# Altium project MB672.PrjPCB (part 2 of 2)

## Sheet MCU.SchDoc: STM3210E-EVAL MCU
size A3; Date: Not used; ApprovedBy: Not used; CheckedBy: Not used; Author: Not used; CompanyName: STMicroelectronics; DrawnBy: Not used; Engineer: Not used; Organization: Not used; Address1: Not used; Address2: Not used; Address3: Not used; Address4: Not used; DocumentNumber: Not used; Revision: Not used; SheetNumber: 3; SheetTotal: 12
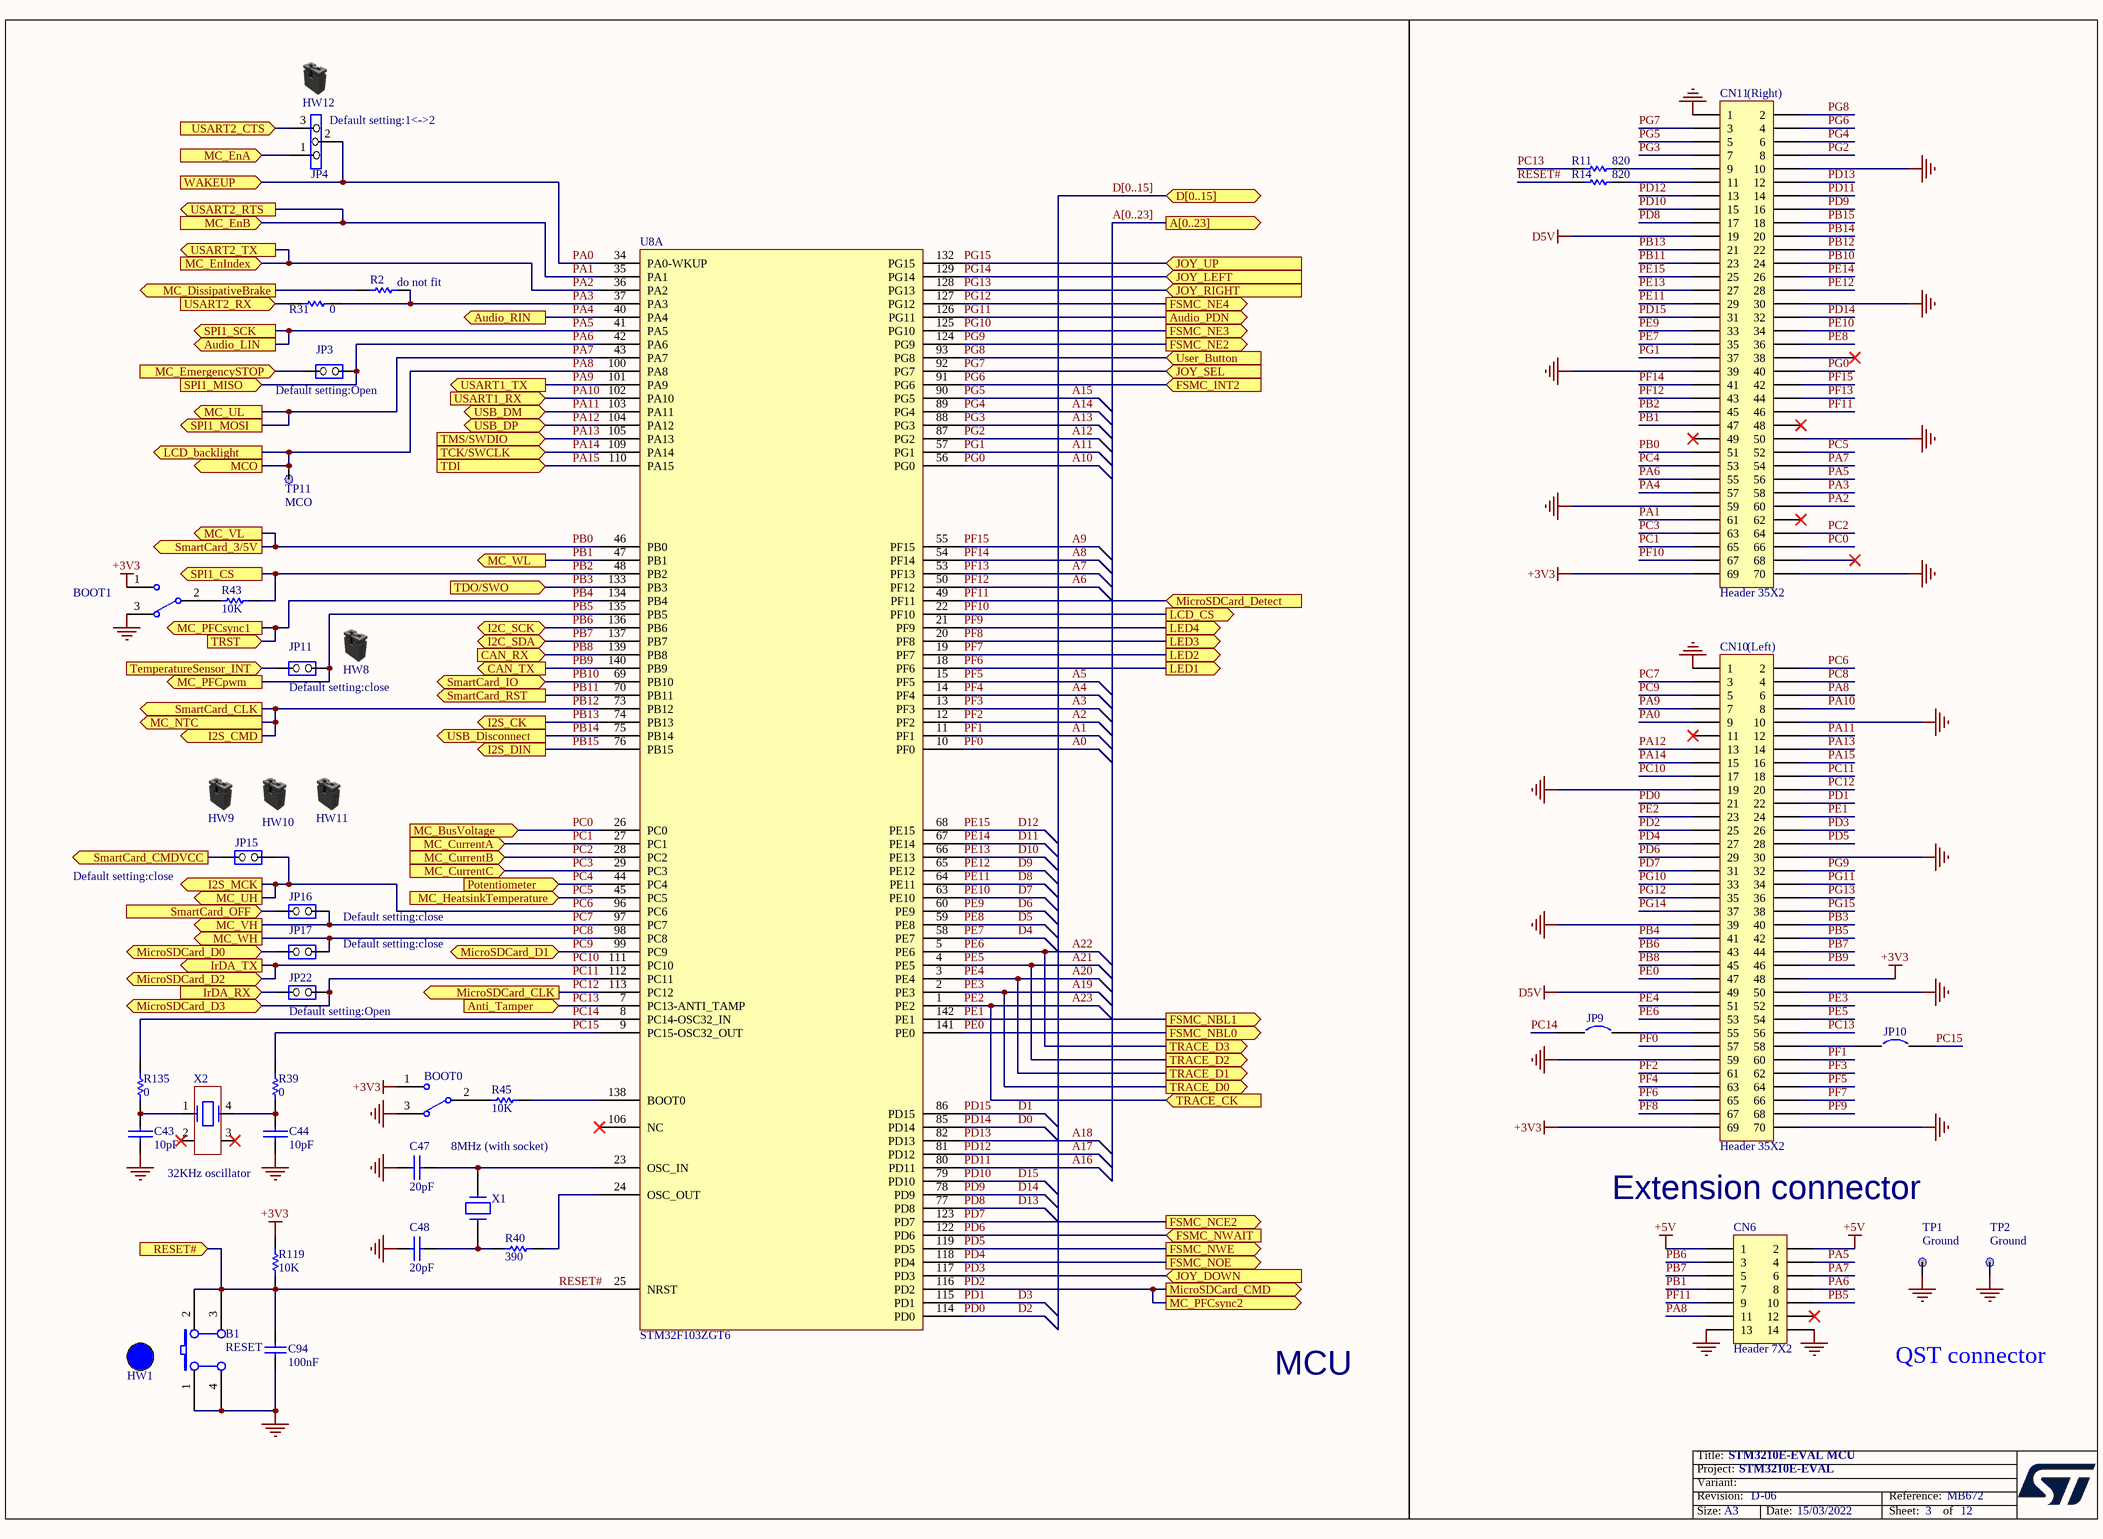
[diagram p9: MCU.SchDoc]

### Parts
B1  RESET  [PB10]
BOOT0  (no value)  [SIP3]
BOOT1  (no value)  [SIP3]
C43  10pF  [0603]
C44  10pF  [0603]
C47  20pF  [0603]
C48  20pF  [0603]
C94  100nF  [0603P]
CN6  Header 7X2  [HDR2X7]
CN10  Header 35X2
CN11  Header 35X2
HW1  BUTTON_HAT_BLUE  (value not drawn)  (mechanical)
HW8  Shunt Black 2.54mm  (value not drawn)  (mechanical)
HW9  Shunt Black 2.54mm  (value not drawn)  (mechanical)
HW10  Shunt Black 2.54mm  (value not drawn)  (mechanical)
HW11  Shunt Black 2.54mm  (value not drawn)  (mechanical)
HW12  Shunt Black 2.54mm  (value not drawn)  (mechanical)
JP3  (no value)  [SIP2]
JP4  (no value)  [SIP3]
JP9  (no value)  [SPST-2]
JP10  (no value)  [SPST-2]
JP11  (no value)  [SIP2]
JP15  (no value)  [SIP2]
JP16  (no value)  [SIP2]
JP17  (no value)  [SIP2]
JP22  (no value)  [SIP2]
R2  do not fit  [0603]
R11  820  [0603]
R14  820  [0603]
R31  0  [0603]
R39  0  [0805]
R40  390  [0603]
R43  10K  [0603]
R45  10K  [0603]
R119  10K  [0603]
R135  0  [0805]
TP1  Ground  [TP]
TP2  Ground  [TP]
TP11  MCO  [TP]
U8  STM32F103ZGT6  (part A of 2)
X1  8MHz (with socket)  [XTAL1]
X2  32KHz oscillator  [SM8]

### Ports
A[0..23] (out), Anti_Tamper (in), Audio_LIN (out), Audio_PDN (out), Audio_RIN (out), CAN_RX (in), CAN_TX (out), D[0..15] (bidir), FSMC_INT2 (in), FSMC_NBL0 (out), FSMC_NBL1 (out), FSMC_NCE2 (out), FSMC_NE2 (out), FSMC_NE3 (out), FSMC_NE4 (out), FSMC_NOE (out), FSMC_NWAIT (in), FSMC_NWE (out), I2C_SCK (bidir), I2C_SDA (bidir), I2S_CK (out), I2S_CMD (out), I2S_DIN (out), I2S_MCK (out), IrDA_RX (in), IrDA_TX (out), JOY_DOWN (in), JOY_LEFT (in), JOY_RIGHT (in), JOY_SEL (in), JOY_UP (in), LCD_backlight (out), LCD_CS (out), LED1 (out), LED2 (out), LED3 (out), LED4 (out), MC_BusVoltage (in), MC_CurrentA (in), MC_CurrentB (in), MC_CurrentC (in), MC_DissipativeBrake (out), MC_EmergencySTOP (in), MC_EnA (in), MC_EnB (in), MC_EnIndex (in), MC_HeatsinkTemperature (in), MC_NTC (out), MC_PFCpwm (out), MC_PFCsync1 (out), MC_PFCsync2 (out), MC_UH (out), MC_UL (out), MC_VH (out), MC_VL (out), MC_WH (out), MC_WL (out), MCO (out), MicroSDCard_CLK (out), MicroSDCard_CMD (out), MicroSDCard_D0 (bidir), MicroSDCard_D1 (bidir), MicroSDCard_D2 (bidir), MicroSDCard_D3 (bidir), MicroSDCard_Detect (in), Potentiometer (in), RESET# (in), SmartCard_3/5V (out), SmartCard_CLK (out), SmartCard_CMDVCC (out), SmartCard_IO (bidir), SmartCard_OFF (in), SmartCard_RST (out), SPI1_CS (out), SPI1_MISO (in), SPI1_MOSI (out), SPI1_SCK (out), TCK/SWCLK (in), TDI (in), TDO/SWO (in), TemperatureSensor_INT (in), TMS/SWDIO (in), TRACE_CK (in), TRACE_D0 (out), TRACE_D1 (out), TRACE_D2 (out), TRACE_D3 (out), TRST (in), USART1_RX (in), USART1_TX (out), USART2_CTS (in), USART2_RTS (out), USART2_RX (in), USART2_TX (out), USB_Disconnect (out), USB_DM (bidir), USB_DP (bidir), User_Button (in), WAKEUP (in)

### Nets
+3V3: BOOT0.1 BOOT1.1 CN10.48 CN10.69 CN11.69 R119.2
+5V: CN6.1 CN6.2
D5V: CN10.49 CN11.19
GND: B1.1(A0) B1.4(A1) BOOT0.3 BOOT1.3 C43.2 C44.2 C47.2 C48.2 C94.1 CN6.13 CN6.14 CN10.1 CN10.10 CN10.19 CN10.30 CN10.39 CN10.50 CN10.59 CN10.70 CN11.1 CN11.10 CN11.30 CN11.39 CN11.50 CN11.59 CN11.70 TP1.1 TP2.1
A0: CN10.57 U8.10(PF0)  [also labelled PF0]
A1: CN10.60 U8.11(PF1)  [also labelled PF1]
A2: CN10.61 U8.12(PF2)  [also labelled PF2]
A3: CN10.62 U8.13(PF3)  [also labelled PF3]
A4: CN10.63 U8.14(PF4)  [also labelled PF4]
A5: CN10.64 U8.15(PF5)  [also labelled PF5]
A6: CN11.43 U8.50(PF12)  [also labelled PF12]
A7: CN11.44 U8.53(PF13)  [also labelled PF13]
A8: CN11.41 U8.54(PF14)  [also labelled PF14]
A9: CN11.42 U8.55(PF15)  [also labelled PF15]
A10: CN11.40 U8.56(PG0)  [also labelled PG0]
A11: CN11.37 U8.57(PG1)  [also labelled PG1]
A12: CN11.8 U8.87(PG2)  [also labelled PG2]
A13: CN11.7 U8.88(PG3)  [also labelled PG3]
A14: CN11.6 U8.89(PG4)  [also labelled PG4]
A15: CN11.5 U8.90(PG5)  [also labelled PG5]
A16: CN11.14 U8.80(PD11)  [also labelled PD11]
A17: CN11.13 U8.81(PD12)  [also labelled PD12]
A18: CN11.12 U8.82(PD13)  [also labelled PD13]
A19: CN10.52 U8.2(PE3) ; port TRACE_D0  [also labelled PE3]
A20: CN10.51 U8.3(PE4) ; port TRACE_D1  [also labelled PE4]
A21: CN10.54 U8.4(PE5) ; port TRACE_D2  [also labelled PE5]
A22: CN10.53 U8.5(PE6) ; port TRACE_D3  [also labelled PE6]
A23: CN10.23 U8.1(PE2) ; port TRACE_CK  [also labelled PE2]
D0: CN11.32 U8.85(PD14)  [also labelled PD14]
D1: CN11.31 U8.86(PD15)  [also labelled PD15]
D2: CN10.21 U8.114(PD0)  [also labelled PD0]
D3: CN10.22 U8.115(PD1)  [also labelled PD1]
D4: CN11.35 U8.58(PE7)  [also labelled PE7]
D5: CN11.36 U8.59(PE8)  [also labelled PE8]
D6: CN11.33 U8.60(PE9)  [also labelled PE9]
D7: CN11.34 U8.63(PE10)  [also labelled PE10]
D8: CN11.29 U8.64(PE11)  [also labelled PE11]
D9: CN11.28 U8.65(PE12)  [also labelled PE12]
D10: CN11.27 U8.66(PE13)  [also labelled PE13]
D11: CN11.26 U8.67(PE14)  [also labelled PE14]
D12: CN11.25 U8.68(PE15)  [also labelled PE15]
D13: CN11.17 U8.77(PD8)  [also labelled PD8]
D14: CN11.16 U8.78(PD9)  [also labelled PD9]
D15: CN11.15 U8.79(PD10)  [also labelled PD10]
PA0: CN10.9 JP4.2 U8.34(PA0-WKUP) ; port WAKEUP
PA1: CN11.61 U8.35(PA1) ; port USART2_RTS, port MC_EnB
PA2: CN11.60 U8.36(PA2) ; port USART2_TX, port MC_EnIndex
PA3: CN11.58 R2.1 R31.1 U8.37(PA3)
PA4: CN11.57 U8.40(PA4) ; port Audio_RIN
PA5: CN6.4 CN11.56 U8.41(PA5) ; port SPI1_SCK, port Audio_LIN
PA6: CN6.8 CN11.55 JP3.1(COMMON) U8.42(PA6) ; port SPI1_MISO
PA7: CN6.6 CN11.54 U8.43(PA7) ; port MC_UL, port SPI1_MOSI
PA8: CN6.11 CN10.6 TP11.1 U8.100(PA8) ; port LCD_backlight, port MCO
PA9: CN10.7 U8.101(PA9) ; port USART1_TX
PA10: CN10.8 U8.102(PA10) ; port USART1_RX
PA11: CN10.12 U8.103(PA11) ; port USB_DM
PA12: CN10.13 U8.104(PA12) ; port USB_DP
PA13: CN10.14 U8.105(PA13) ; port TMS/SWDIO
PA14: CN10.15 U8.109(PA14) ; port TCK/SWCLK
PA15: CN10.16 U8.110(PA15) ; port TDI
PB0: CN11.51 U8.46(PB0) ; port MC_VL, port SmartCard_3/5V
PB1: CN6.7 CN11.47 U8.47(PB1) ; port MC_WL
PB2: CN11.45 R43.1 U8.48(PB2) ; port SPI1_CS
PB3: CN10.40 U8.133(PB3) ; port TDO/SWO
PB4: CN10.41 U8.134(PB4) ; port TRST, port MC_PFCsync1
PB5: CN6.10 CN10.42 JP11.1(COMMON) U8.135(PB5) ; port MC_PFCpwm
PB6: CN6.3 CN10.43 U8.136(PB6) ; port I2C_SCK
PB7: CN6.5 CN10.44 U8.137(PB7) ; port I2C_SDA
PB8: CN10.45 U8.139(PB8) ; port CAN_RX
PB9: CN10.46 U8.140(PB9) ; port CAN_TX
PB10: CN11.24 U8.69(PB10) ; port SmartCard_IO
PB11: CN11.23 U8.70(PB11) ; port SmartCard_RST
PB12: CN11.22 U8.73(PB12) ; port I2S_CMD, port MC_NTC, port SmartCard_CLK
PB13: CN11.21 U8.74(PB13) ; port I2S_CK
PB14: CN11.20 U8.75(PB14) ; port USB_Disconnect
PB15: CN11.18 U8.76(PB15) ; port I2S_DIN
PC0: CN11.66 U8.26(PC0) ; port MC_BusVoltage
PC1: CN11.65 U8.27(PC1) ; port MC_CurrentA
PC2: CN11.64 U8.28(PC2) ; port MC_CurrentB
PC3: CN11.63 U8.29(PC3) ; port MC_CurrentC
PC4: CN11.53 U8.44(PC4) ; port Potentiometer
PC5: CN11.52 U8.45(PC5) ; port MC_HeatsinkTemperature
PC6: CN10.2 JP15.1(COMMON) U8.96(PC6) ; port MC_UH, port I2S_MCK
PC7: CN10.3 JP16.1(COMMON) U8.97(PC7) ; port MC_VH
PC8: CN10.4 JP17.1(COMMON) U8.98(PC8) ; port MC_WH
PC9: CN10.5 U8.99(PC9) ; port MicroSDCard_D1
PC10: CN10.17 U8.111(PC10) ; port IrDA_TX, port MicroSDCard_D2
PC11: CN10.18 JP22.1(COMMON) U8.112(PC11) ; port MicroSDCard_D3
PC12: CN10.20 U8.113(PC12) ; port MicroSDCard_CLK
PC13: CN10.56 R11.1 U8.7(PC13-ANTI_TAMP) ; port Anti_Tamper
PC14: JP9.1 R135.2 U8.8(PC14-OSC32_IN)
PC15: JP10.2 R39.2 U8.9(PC15-OSC32_OUT)
PD2: CN10.25 U8.116(PD2) ; port MC_PFCsync2, port MicroSDCard_CMD
PD3: CN10.26 U8.117(PD3) ; port JOY_DOWN
PD4: CN10.27 U8.118(PD4) ; port FSMC_NOE
PD5: CN10.28 U8.119(PD5) ; port FSMC_NWE
PD6: CN10.29 U8.122(PD6) ; port FSMC_NWAIT
PD7: CN10.31 U8.123(PD7) ; port FSMC_NCE2
PE0: CN10.47 U8.141(PE0) ; port FSMC_NBL0
PE1: CN10.24 U8.142(PE1) ; port FSMC_NBL1
PF6: CN10.65 U8.18(PF6) ; port LED1
PF7: CN10.66 U8.19(PF7) ; port LED2
PF8: CN10.67 U8.20(PF8) ; port LED3
PF9: CN10.68 U8.21(PF9) ; port LED4
PF10: CN11.67 U8.22(PF10) ; port LCD_CS
PF11: CN6.9 CN11.46 U8.49(PF11) ; port MicroSDCard_Detect
PG6: CN11.4 U8.91(PG6) ; port FSMC_INT2
PG7: CN11.3 U8.92(PG7) ; port JOY_SEL
PG8: CN11.2 U8.93(PG8) ; port User_Button
PG9: CN10.32 U8.124(PG9) ; port FSMC_NE2
PG10: CN10.33 U8.125(PG10) ; port FSMC_NE3
PG11: CN10.34 U8.126(PG11) ; port Audio_PDN
PG12: CN10.35 U8.127(PG12) ; port FSMC_NE4
PG13: CN10.36 U8.128(PG13) ; port JOY_RIGHT
PG14: CN10.37 U8.129(PG14) ; port JOY_LEFT
PG15: CN10.38 U8.132(PG15) ; port JOY_UP
RESET#: B1.2(B0) B1.3(B1) C94.2 R14.2 R119.1 U8.25(NRST) ; port RESET#
NetBOOT0_2: BOOT0.2 R45.2
NetBOOT1_2: BOOT1.2 R43.2
NetC1_2: JP4.1 ; port MC_EnA
NetC43_1: C43.1 R135.1 X2.1
NetC44_1: C44.1 R39.1 X2.4
NetC47_1: C47.1 U8.23(OSC_IN) X1.2
NetC48_1: C48.1 R40.2 X1.1
NetCN1_23: R2.2 ; port MC_DissipativeBrake
NetCN10_55: CN10.55 JP9.2
NetCN10_58: CN10.58 JP10.1
NetCN11_9: CN11.9 R11.2
NetCN11_11: CN11.11 R14.1
NetCN13_7: JP17.2(NO) ; port MicroSDCard_D0
NetJP3_2: JP3.2(NO) ; port MC_EmergencySTOP
NetJP4_3: JP4.3 ; port USART2_CTS
NetJP11_2: JP11.2(NO) ; port TemperatureSensor_INT
NetJP15_2: JP15.2(NO) ; port SmartCard_CMDVCC
NetJP16_2: JP16.2(NO) ; port SmartCard_OFF
NetJP22_2: JP22.2(NO) ; port IrDA_RX
NetR29_2: R31.2 ; port USART2_RX
NetR40_1: R40.1 U8.24(OSC_OUT)
NetR45_1: R45.1 U8.138(BOOT0)

Not connected (* = marked no-connect by the designer): CN6 12*; CN10 11*; CN11 38* 48* 49* 62* 68*; U8 106(NC)*; X2 2* 3*

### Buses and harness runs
bus A[0..23] = port A[0..23]
bus D[0..15] = port D[0..15]

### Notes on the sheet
- (near JP4) Default setting:1<->2
- (near CN11) (Right)
- (near JP3) Default setting:Open
- (near CN10) (Left)
- (near JP11) Default setting:close
- (near JP15) Default setting:close
- Default setting:close
- (near JP22) Default setting:Open
- Extension connector
- MCU
- QST connector

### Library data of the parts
B1 = SW PUSHBUTTON: SE PUSHBUTTON
BOOT0 BOOT1 = SW-SPDT: SPDT Subminiature Toggle Switch, Right Angle Mounting, Vertical Actuation; Revision 1: Jul-2002: Re-released for DXP Platform.; Revision 2: 17-Dec-2003: Schematic revised, PCB Footprint replaced.
C43 C44 C47 C48 = CAP: Capacitor
C94 = CAP: Capacitor; Value: 100pF
CN6 = Header 7X2: Header, 7-Pin, Dual row
CN10 CN11 = Header35X2
JP3 JP11 JP15-JP17 JP22 = JP2
JP4 = Jumper3
JP9 JP10 = Circuit Breaker
R2 R31 R43 R45 R119 = res1: Resistor; Value: 1K
R11 R14 R39 R40 R135 = Res1: Resistor; Value: 1K
TP1 TP2 TP11 = TP
U8 = BigPiranha_new
X1 = CRYSTAL
X2 = MC306

## Sheet SD&Smart_Card.SchDoc: STM3210E-EVAL SD&Smart Card
size A4; Date: Not used; ApprovedBy: Not used; CheckedBy: Not used; Author: Not used; CompanyName: STMicroelectronics; DrawnBy: Not used; Engineer: Not used; Organization: Not used; Address1: Not used; Address2: Not used; Address3: Not used; Address4: Not used; DocumentNumber: Not used; Revision: Not used; SheetNumber: 5; SheetTotal: 12
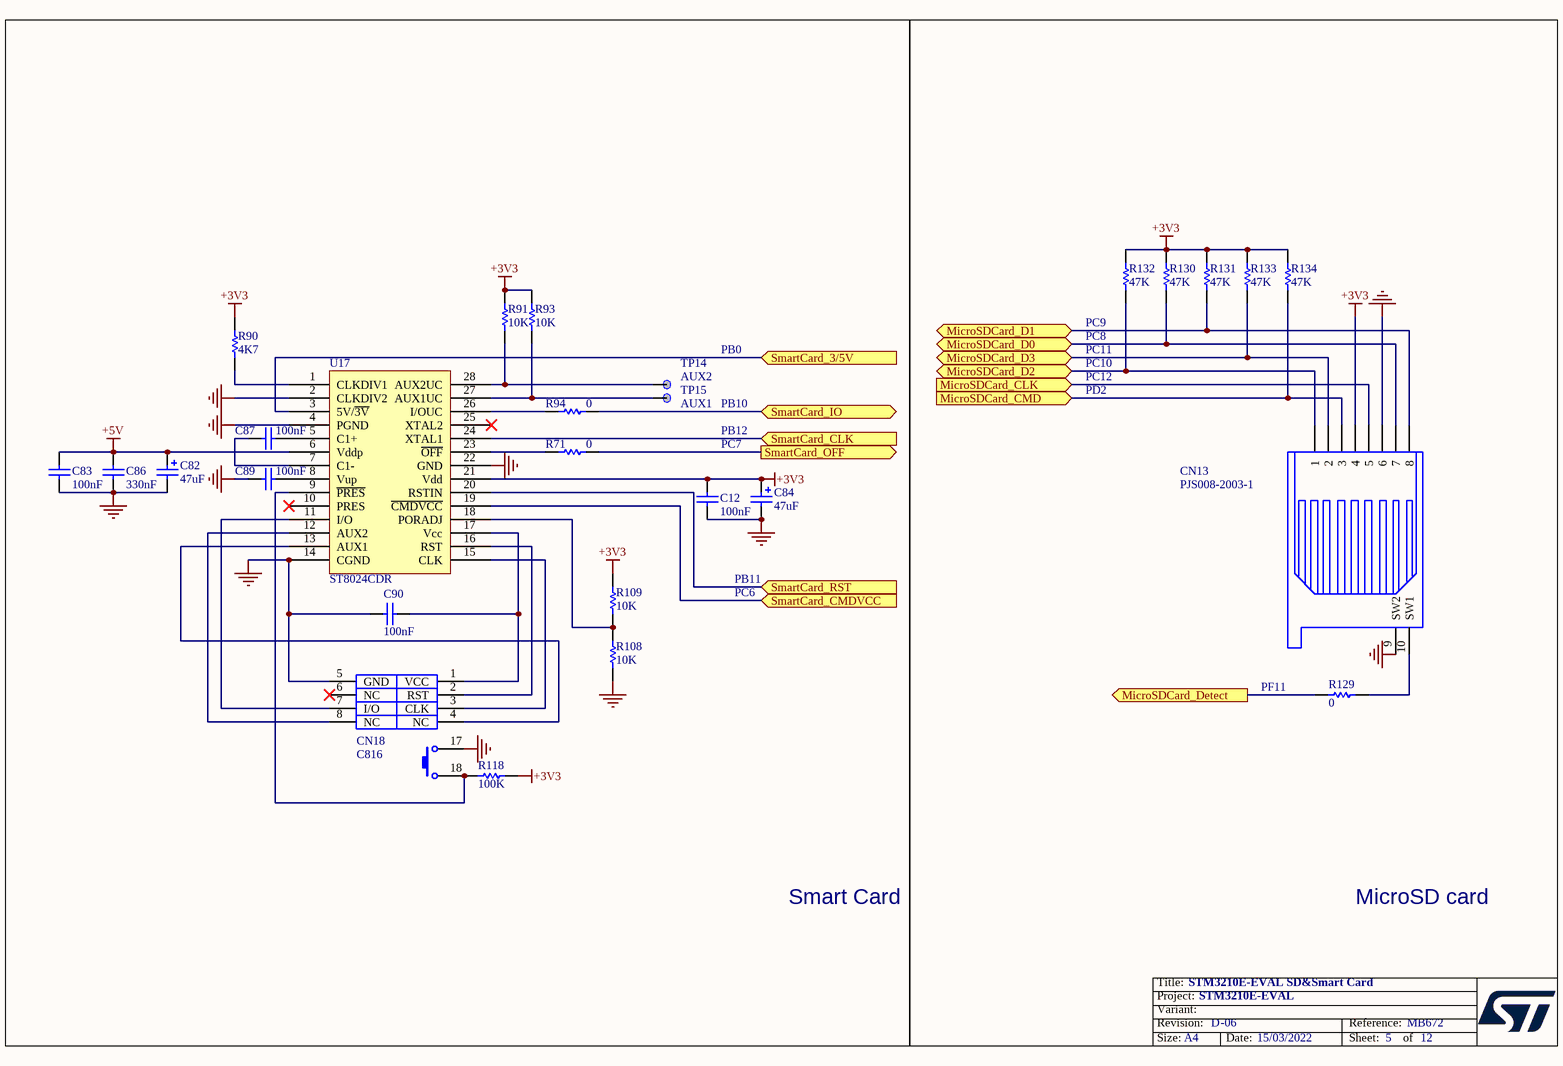
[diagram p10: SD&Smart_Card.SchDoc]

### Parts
C12  100nF  [0603P]
C82  47uF  [TAN-B]
C83  100nF  [0603P]
C84  47uF  [TAN-B]
C86  330nF  [0603]
C87  100nF  [0603P]
C89  100nF  [0603P]
C90  100nF  [0603P]
CN13  PJS008-2003-1  [MSD(PJS008)]
CN18  C816  [SAM(C816)]
R71  0  [0805]
R90  4K7  [0603]
R91  10K  [0603]
R93  10K  [0603]
R94  0  [0805]
R108  10K  [0603]
R109  10K  [0603]
R118  100K  [0603]
R129  0  [0603]
R130  47K  [0805]
R131  47K  [0805]
R132  47K  [0805]
R133  47K  [0805]
R134  47K  [0805]
TP14  AUX2  [TP]
TP15  AUX1  [TP]
U17  ST8024CDR  [SO28]

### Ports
MicroSDCard_CLK (in), MicroSDCard_CMD (in), MicroSDCard_D0 (bidir), MicroSDCard_D1 (bidir), MicroSDCard_D2 (bidir), MicroSDCard_D3 (bidir), MicroSDCard_Detect (out), SmartCard_3/5V (in), SmartCard_CLK (in), SmartCard_CMDVCC (in), SmartCard_IO (bidir), SmartCard_OFF (out), SmartCard_RST (in)

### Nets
+3V3: C12.1 C84.1 CN13.4 R90.1 R91.1 R93.1 R109.1 R118.1 R130.1 R131.1 R132.1 R133.1 R134.1 U17.21(Vdd)
+5V: C82.1 C83.1 C86.1 U17.6(Vddp)
GND: C12.2 C82.2 C83.2 C84.2 C86.2 C89.2 C90.1 CN13.6 CN13.9(SW2) CN18.5(GND) CN18.17 R108.2 U17.2(CLKDIV2) U17.4(PGND) U17.14(CGND) U17.22(GND)
PB0: U17.3(5V/~{3V}) ; port SmartCard_3/5V
PB10: R94.2 ; port SmartCard_IO
PB11: U17.20(RSTIN) ; port SmartCard_RST
PB12: U17.24(XTAL1) ; port SmartCard_CLK
PC9: CN13.8 R131.2 ; port MicroSDCard_D1
PC10: CN13.1 R132.2 ; port MicroSDCard_D2
PC11: CN13.2 R133.2 ; port MicroSDCard_D3
PC12: CN13.5 ; port MicroSDCard_CLK
PD2: CN13.3 R134.2 ; port MicroSDCard_CMD
PF11: R129.1 ; port MicroSDCard_Detect
NetC87_1: C87.1 U17.7(C1-)
NetC87_2: C87.2 U17.5(C1+)
NetC89_1: C89.1 U17.8(Vup)
NetC90_2: C90.2 CN18.1(VCC) U17.17(Vcc)
NetCN13_7: CN13.7 R130.2 ; port MicroSDCard_D0
NetCN13_10: CN13.10(SW1) R129.2
NetCN18_2: CN18.2(RST) U17.16(RST)
NetCN18_3: CN18.3(CLK) U17.15(CLK)
NetCN18_4: CN18.4(NC) U17.13(AUX1)
NetCN18_7: CN18.7(I/O) U17.11(I/O)
NetCN18_8: CN18.8(NC) U17.12(AUX2)
NetCN18_18: CN18.18 R118.2 U17.9(~{PRES})
NetJP15_2: U17.19(~{CMDVCC}) ; port SmartCard_CMDVCC
NetJP16_2: R71.1 ; port SmartCard_OFF
NetR71_2: R71.2 U17.23(~{OFF})
NetR90_2: R90.2 U17.1(CLKDIV1)
NetR91_2: R91.2 TP14.1 U17.28(AUX2UC)
NetR93_2: R93.2 TP15.1 U17.27(AUX1UC)
NetR94_1: R94.1 U17.26(I/OUC)
NetR108_1: R108.1 R109.2 U17.18(PORADJ)

Not connected (* = marked no-connect by the designer): CN18 6(NC)*; U17 10(PRES)* 25(XTAL2)*

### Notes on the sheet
- (near R132) PC9
- PB0
- (near R132) PC8
- PC10
- PC11
- PD2
- PC12
- PB12
- PC7
- PB10
- PC6
- PB11
- PF11
- Smart Card
- MicroSD card

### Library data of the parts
C12 C83 C87 C89 C90 = CAP: Capacitor
C82 C84 = Cap Pol1: Polarized Capacitor (Radial); Value: 100pF
C86 = CAP: Capacitor; Value: 100nF
CN13 = SMS016AFA5E
CN18 = Smart_card_CN
R71 R90 R91 R93 R94 R108 R109 R118 R129-R134 = Res1: Resistor; Value: 1K
TP14 TP15 = TP
U17 = ST8024CTR

## Sheet LCD&Joystick.SchDoc: STM3210E-EVAL LCD&Joystick
size A4; Date: Not used; ApprovedBy: Not used; CheckedBy: Not used; Author: Not used; CompanyName: STMicroelectronics; DrawnBy: Not used; Engineer: Not used; Organization: Not used; Address1: Not used; Address2: Not used; Address3: Not used; Address4: Not used; DocumentNumber: Not used; Revision: Not used; SheetNumber: 8; SheetTotal: 12
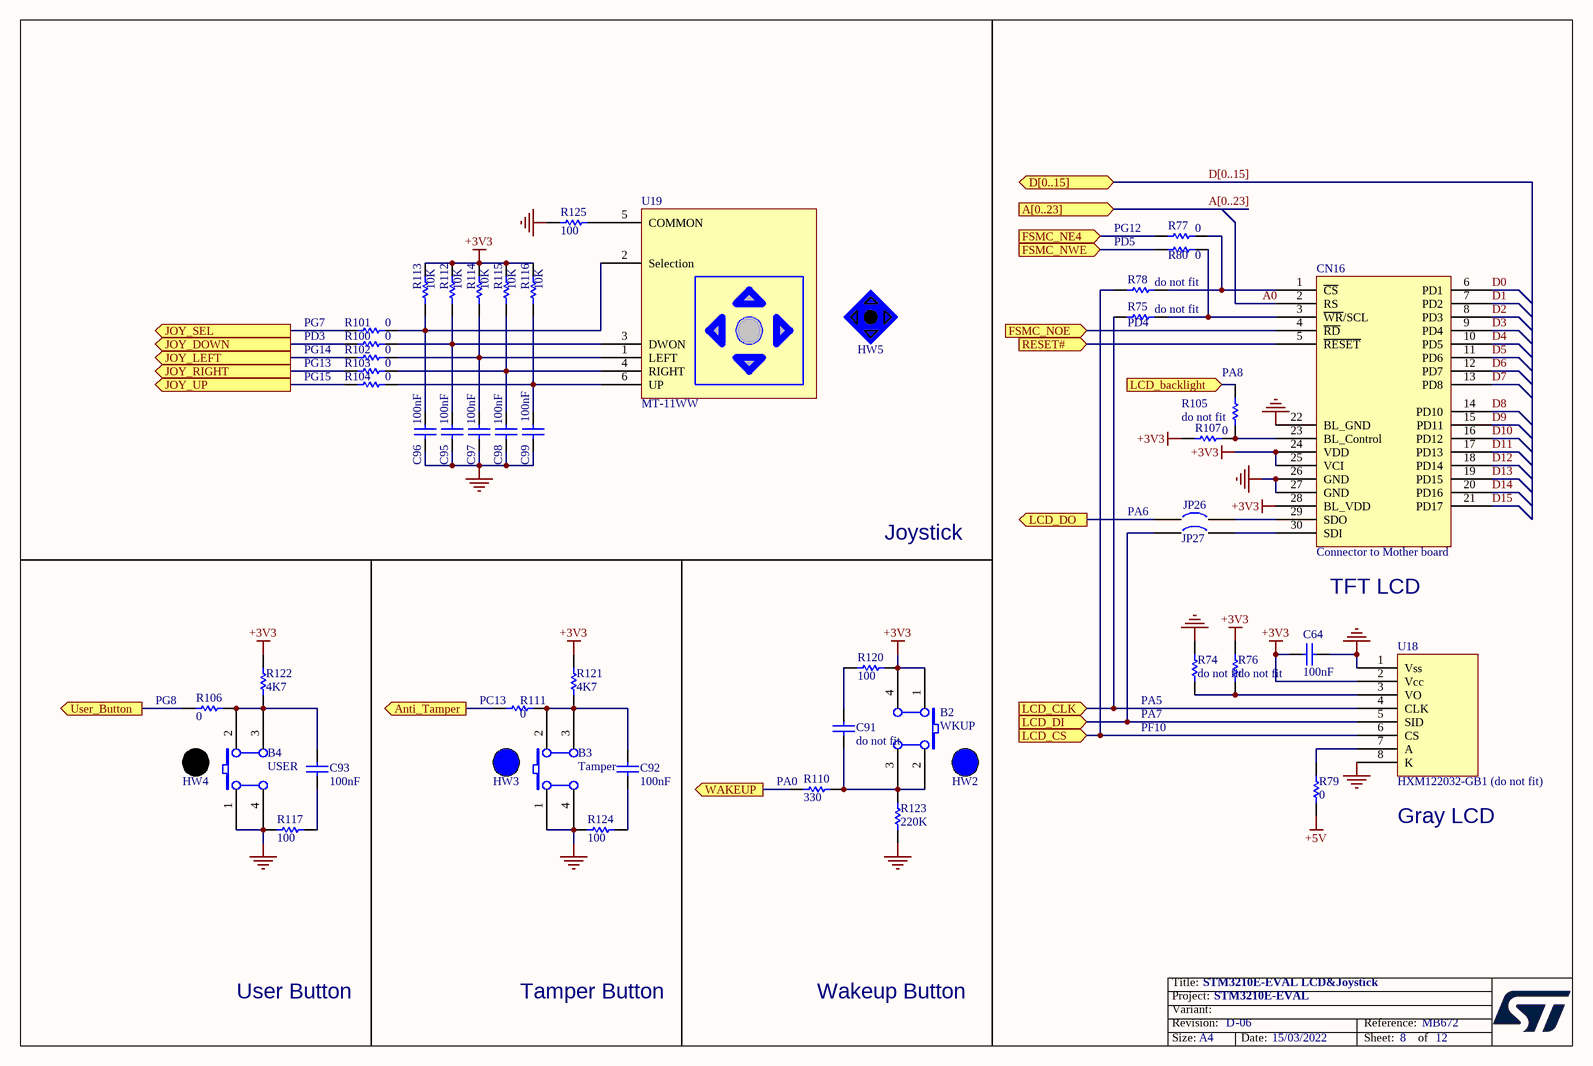
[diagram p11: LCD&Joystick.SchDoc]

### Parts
B2  WKUP  [PB10]
B3  Tamper  [PB10]
B4  USER  [PB10]
C64  100nF  [0603P]
C91  do not fit  [0603P]
C92  100nF  [0603P]
C93  100nF  [0603P]
C95  100nF  [0603P]
C96  100nF  [0603P]
C97  100nF  [0603P]
C98  100nF  [0603P]
C99  100nF  [0603P]
CN16  Connector to Mother board  [AM240320A]
HW2  BUTTON_HAT_BLUE  (value not drawn)  (mechanical)
HW3  BUTTON_HAT_BLUE  (value not drawn)  (mechanical)
HW4  BUTTON_HAT_BLACK  (value not drawn)  (mechanical)
HW5  JOYSTICK_BLUE_HAT  (value not drawn)  (mechanical)
JP26  (no value)  [SPST-2]
JP27  (no value)  [SPST-2]
R74  do not fit  [0603]
R75  do not fit  [0603]
R76  do not fit  [0603]
R77  0  [0603]
R78  do not fit  [0603]
R79  0  [0603]
R80  0  [0603]
R100  0  [0805]
R101  0  [0805]
R102  0  [0805]
R103  0  [0805]
R104  0  [0805]
R105  do not fit  [0603]
R106  0  [0805]
R107  0  [0603]
R110  330  [0805]
R111  0  [0805]
R112  10K  [0603]
R113  10K  [0603]
R114  10K  [0603]
R115  10K  [0603]
R116  10K  [0603]
R117  100  [0603]
R120  100  [0603]
R121  4K7  [0603]
R122  4K7  [0603]
R123  220K  [0603]
R124  100  [0603]
R125  100  [0603]
U18  HXM122032-GB1 (do not fit)  [LCD12232-GB1]
U19  MT-11WW  [JOY]

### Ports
A[0..23] (in), Anti_Tamper (out), D[0..15] (bidir), FSMC_NE4 (in), FSMC_NOE (in), FSMC_NWE (in), JOY_DOWN (out), JOY_LEFT (out), JOY_RIGHT (out), JOY_SEL (out), JOY_UP (out), LCD_backlight (in), LCD_CLK (in), LCD_CS (in), LCD_DI (in), LCD_DO (out), RESET# (in), User_Button (out), WAKEUP (out)

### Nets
+3V3: B2.1(A0) B2.4(A1) C64.1 CN16.24(VDD) CN16.25(VCI) CN16.28(BL_VDD) R76.2 R107.2 R112.2 R113.1 R114.2 R115.2 R116.2 R120.1 R121.2 R122.2 U18.2(Vcc)
+5V: R79.1
GND: B3.1(A0) B3.4(A1) B4.1(A0) B4.4(A1) C64.2 C95.1 C96.1 C97.1 C98.1 C99.1 CN16.22(BL_GND) CN16.26(GND) CN16.27(GND) R74.1 R117.1 R123.2 R124.1 R125.1 U18.1(Vss) U18.8(K)
A0: CN16.2(RS)
D0: CN16.6(PD1)
D1: CN16.7(PD2)
D2: CN16.8(PD3)
D3: CN16.9(PD4)
D4: CN16.10(PD5)
D5: CN16.11(PD6)
D6: CN16.12(PD7)
D7: CN16.13(PD8)
D8: CN16.14(PD10)
D9: CN16.15(PD11)
D10: CN16.16(PD12)
D11: CN16.17(PD13)
D12: CN16.18(PD14)
D13: CN16.19(PD15)
D14: CN16.20(PD16)
D15: CN16.21(PD17)
PA0: R110.2 ; port WAKEUP
PA8: R105.2 ; port LCD_backlight
PC13: R111.2 ; port Anti_Tamper
PD3: R100.2 ; port JOY_DOWN
PD4: CN16.4(~{RD}) ; port FSMC_NOE
PD5: R80.1 ; port FSMC_NWE
PF10: R78.1 U18.6(CS) ; port LCD_CS
PG7: R101.2 ; port JOY_SEL
PG8: R106.2 ; port User_Button
PG12: R77.1 ; port FSMC_NE4
PG13: R103.2 ; port JOY_RIGHT
PG14: R102.2 ; port JOY_LEFT
PG15: R104.2 ; port JOY_UP
RESET#: CN16.5(~{RESET}) ; port RESET#
NetB2_2: B2.2(B0) B2.3(B1) C91.2 R110.1 R123.1
NetB3_2: B3.2(B0) B3.3(B1) C92.2 R111.1 R121.1
NetB4_2: B4.2(B0) B4.3(B1) C93.2 R106.1 R122.1
NetC91_1: C91.1 R120.2
NetC92_1: C92.1 R124.2
NetC93_1: C93.1 R117.2
NetC95_2: C95.2 R100.1 R112.1 U19.3(DWON)
NetC96_2: C96.2 R101.1 R113.2 U19.2(Selection)
NetC97_2: C97.2 R102.1 R114.1 U19.1(LEFT)
NetC98_2: C98.2 R103.1 R115.1 U19.4(RIGHT)
NetC99_2: C99.2 R104.1 R116.1 U19.6(UP)
NetCN16_1: CN16.1(~{CS}) R77.2 R78.2
NetCN16_3: CN16.3(~{WR}/SCL) R75.1 R80.2
NetCN16_23: CN16.23(BL_Control) R105.1 R107.1
NetCN16_29: CN16.29(SDO) JP26.2
NetCN16_30: CN16.30(SDI) JP27.2
NetJP26_1: JP26.1 ; port LCD_DO
NetJP27_1: JP27.1 U18.5(SID) ; port LCD_DI
NetR74_2: R74.2 R76.1 U18.3(VO)
NetR75_2: R75.2 U18.4(CLK) ; port LCD_CLK
NetR79_2: R79.2 U18.7(A)
NetR125_2: R125.2 U19.5(COMMON)

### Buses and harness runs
bus A[0..23] = port A[0..23]
bus D[0..15] = port D[0..15]

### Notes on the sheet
- PG12
- PD5
- PG7
- (near R75) PD4
- PD3
- PG14
- PG13
- PG15
- (near R105) PA8
- PA6
- Joystick
- TFT LCD
- (near R106) PG8
- (near R111) PC13
- (near R74) PA5
- (near R74) PA7
- (near R74) PF10
- (near R110) PA0
- (near U18) Gray LCD
- User Button
- Tamper Button
- Wakeup Button

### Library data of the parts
B2-B4 = SW PUSHBUTTON: SE PUSHBUTTON
C64 C91-C93 C95-C99 = CAP: Capacitor; Value: 100pF
CN16 = ColorLCD_module
JP26 JP27 = Circuit Breaker
R74-R80 R100-R107 R110-R117 R120 R124 R125 = Res1: Resistor; Value: 1K
R121-R123 = res1: Resistor; Value: 1K
U18 = HXM122032-GB1
U19 = MT-008A

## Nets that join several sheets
+3V3: Audio (9 pins), SRAM&Flash (23 pins), RS232&IrDA (10 pins), Peripherals (17 pins), MotorCtrl (CN1.28 R7.2), Power (6 pins), JTAG&SWD (8 pins), MCU (6 pins), SD&Smart_Card (14 pins), LCD&Joystick (17 pins)
+5V: MotorCtrl (CN1.25), Power (7 pins), MCU (CN6.1 CN6.2), SD&Smart_Card (C82.1 C83.1 C86.1 U17.6), LCD&Joystick (R79.1)
D5V: Power (JP13.4), MCU (CN10.49 CN11.19)
GND: Audio (19 pins), SRAM&Flash (18 pins), RS232&IrDA (19 pins), Peripherals (43 pins), MotorCtrl (27 pins), Power (38 pins), JTAG&SWD (21 pins), MCU (28 pins), SD&Smart_Card (16 pins), LCD&Joystick (20 pins)
U5V: Peripherals (C74.2 CN14.1 R70.1 U11.5), Power (JP13.2)
A0: SRAM&Flash (U1.A3 U2.E2), MCU (CN10.57 U8.10), LCD&Joystick (CN16.2)
A1: SRAM&Flash (U1.A4 U2.D2), MCU (CN10.60 U8.11)
A2: SRAM&Flash (U1.A5 U2.C2), MCU (CN10.61 U8.12)
A3: SRAM&Flash (U1.B3 U2.A2), MCU (CN10.62 U8.13)
A4: SRAM&Flash (U1.B4 U2.B2), MCU (CN10.63 U8.14)
A5: SRAM&Flash (U1.C3 U2.D3), MCU (CN10.64 U8.15)
A6: SRAM&Flash (U1.C4 U2.C3), MCU (CN11.43 U8.50)
A7: SRAM&Flash (U1.D4 U2.A3), MCU (CN11.44 U8.53)
A8: SRAM&Flash (U1.H2 U2.B6), MCU (CN11.41 U8.54)
A9: SRAM&Flash (U1.H3 U2.A6), MCU (CN11.42 U8.55)
A10: SRAM&Flash (U1.H4 U2.C6), MCU (CN11.40 U8.56)
A11: SRAM&Flash (U1.H5 U2.D6), MCU (CN11.37 U8.57)
A12: SRAM&Flash (U1.G3 U2.B7), MCU (CN11.8 U8.87)
A13: SRAM&Flash (U1.G4 U2.A7), MCU (CN11.7 U8.88)
A14: SRAM&Flash (U1.F3 U2.C7), MCU (CN11.6 U8.89)
A15: SRAM&Flash (U1.F4 U2.D7), MCU (CN11.5 U8.90)
A16: SRAM&Flash (U1.E4 U2.E7 U3.16), MCU (CN11.14 U8.80)
A17: SRAM&Flash (U1.D3 U2.B3 U3.17), MCU (CN11.13 U8.81)
A18: SRAM&Flash (U1.H1 U2.C4), MCU (CN11.12 U8.82)
A19: SRAM&Flash (U2.D5), JTAG&SWD (R49.2), MCU (CN10.52 U8.2)
A20: SRAM&Flash (U2.D4), JTAG&SWD (R60.2), MCU (CN10.51 U8.3)
A21: SRAM&Flash (U2.C5), JTAG&SWD (CN7.18), MCU (CN10.54 U8.4)
A22: SRAM&Flash (U2.B8), JTAG&SWD (CN7.20), MCU (CN10.53 U8.5)
A23: JTAG&SWD (CN7.12), MCU (CN10.23 U8.1)
D0: SRAM&Flash (U1.B6 U2.E3 U3.29), MCU (CN11.32 U8.85), LCD&Joystick (CN16.6)
D1: SRAM&Flash (U1.C5 U2.H3 U3.30), MCU (CN11.31 U8.86), LCD&Joystick (CN16.7)
D2: SRAM&Flash (U1.C6 U2.E4 U3.31), MCU (CN10.21 U8.114), LCD&Joystick (CN16.8)
D3: SRAM&Flash (U1.D5 U2.H4 U3.32), MCU (CN10.22 U8.115), LCD&Joystick (CN16.9)
D4: SRAM&Flash (U1.E5 U2.H5 U3.41), MCU (CN11.35 U8.58), LCD&Joystick (CN16.10)
D5: SRAM&Flash (U1.F5 U2.E5 U3.42), MCU (CN11.36 U8.59), LCD&Joystick (CN16.11)
D6: SRAM&Flash (U1.F6 U2.H6 U3.43), MCU (CN11.33 U8.60), LCD&Joystick (CN16.12)
D7: SRAM&Flash (U1.G6 U2.E6 U3.44), MCU (CN11.34 U8.63), LCD&Joystick (CN16.13)
D8: SRAM&Flash (U1.B1 U2.F3), MCU (CN11.29 U8.64), LCD&Joystick (CN16.14)
D9: SRAM&Flash (U1.C1 U2.G3), MCU (CN11.28 U8.65), LCD&Joystick (CN16.15)
D10: SRAM&Flash (U1.C2 U2.F4), MCU (CN11.27 U8.66), LCD&Joystick (CN16.16)
D11: SRAM&Flash (U1.D2 U2.G4), MCU (CN11.26 U8.67), LCD&Joystick (CN16.17)
D12: SRAM&Flash (U1.E2 U2.F5), MCU (CN11.25 U8.68), LCD&Joystick (CN16.18)
D13: SRAM&Flash (U1.F2 U2.G6), MCU (CN11.17 U8.77), LCD&Joystick (CN16.19)
D14: SRAM&Flash (U1.F1 U2.F6), MCU (CN11.16 U8.78), LCD&Joystick (CN16.20)
D15: SRAM&Flash (U1.G1 U2.G7), MCU (CN11.15 U8.79), LCD&Joystick (CN16.21)
NetC1_2: MotorCtrl (C1.2 CN1.31 JP2.1), MCU (JP4.1)
NetCN1_15: Peripherals (CN5.5 JP25.1), MotorCtrl (CN1.15 R5.2)
NetCN1_17: Peripherals (CN3.5 JP24.1), MotorCtrl (CN1.17 R4.2)
NetCN1_19: Peripherals (CN2.5 JP23.1), MotorCtrl (CN1.19 R3.2)
NetCN1_23: MotorCtrl (CN1.23), MCU (R2.2)
NetCN13_7: MCU (JP17.2), SD&Smart_Card (CN13.7 R130.2)
NetJP3_2: MotorCtrl (R8.2), MCU (JP3.2)
NetJP4_3: RS232&IrDA (R30.2), MCU (JP4.3)
NetJP11_2: Peripherals (R46.2), MCU (JP11.2)
NetJP15_2: MCU (JP15.2), SD&Smart_Card (U17.19)
NetJP16_2: MCU (JP16.2), SD&Smart_Card (R71.1)
NetJP22_2: RS232&IrDA (R89.2), MCU (JP22.2)
NetR29_2: RS232&IrDA (R29.2), MCU (R31.2)
PA0: MCU (CN10.9 JP4.2 U8.34), LCD&Joystick (R110.2)
PA1: RS232&IrDA (U5.10), MotorCtrl (C4.2 CN1.33), MCU (CN11.61 U8.35)
PA2: RS232&IrDA (U5.11), MotorCtrl (C3.2 CN1.34), MCU (CN11.60 U8.36)
PA4: Audio (R67.2), MCU (CN11.57 U8.40)
PA5: Audio (R68.2), MCU (CN6.4 CN11.56 U8.41)
PA7: MotorCtrl (CN1.5), MCU (CN6.6 CN11.54 U8.43)
PA8: Audio (R57.2), MCU (CN6.11 CN10.6 TP11.1 U8.100), LCD&Joystick (R105.2)
PA9: RS232&IrDA (U7.11), MCU (CN10.7 U8.101)
PA10: RS232&IrDA (R36.2), MCU (CN10.8 U8.102)
PA11: Peripherals (R81.1), MCU (CN10.12 U8.103)
PA12: Peripherals (R82.1), MCU (CN10.13 U8.104)
PA13: JTAG&SWD (CN7.2 CN9.7 R58.1), MCU (CN10.14 U8.105)
PA14: JTAG&SWD (CN7.4 CN9.9 R54.2), MCU (CN10.15 U8.109)
PA15: JTAG&SWD (CN7.8 CN9.5 R59.1), MCU (CN10.16 U8.110)
PB0: MotorCtrl (CN1.9), MCU (CN11.51 U8.46), SD&Smart_Card (U17.3)
PB1: MotorCtrl (CN1.13), MCU (CN6.7 CN11.47 U8.47)
PB3: JTAG&SWD (CN7.6 CN9.13 R50.2 R53.1), MCU (CN10.40 U8.133)
PB4: MotorCtrl (C51.2 JP20.2), JTAG&SWD (CN9.3 JP19.1 R61.2 R64.1), MCU (CN10.41 U8.134)
PB5: MotorCtrl (C5.2 CN1.29), MCU (CN6.10 CN10.42 JP11.1 U8.135)
PB8: Peripherals (R32.2), MCU (CN10.45 U8.139)
PB9: Peripherals (U4.1), MCU (CN10.46 U8.140)
PB10: MCU (CN11.24 U8.69), SD&Smart_Card (R94.2)
PB11: MCU (CN11.23 U8.70), SD&Smart_Card (U17.20)
PB12: Audio (U10.13), MotorCtrl (CN1.21), MCU (CN11.22 U8.73), SD&Smart_Card (U17.24)
PB13: Audio (U10.14), MCU (CN11.21 U8.74)
PB14: Peripherals (JP14.3), MCU (CN11.20 U8.75)
PB15: Audio (U10.11), MCU (CN11.18 U8.76)
PC0: MotorCtrl (C7.2 R6.2 R63.2), MCU (CN11.66 U8.26)
PC1: MotorCtrl (C22.2 R5.1), MCU (CN11.65 U8.27)
PC2: MotorCtrl (C13.2 R4.1), MCU (CN11.64 U8.28)
PC3: MotorCtrl (C9.2 R3.1), MCU (CN11.63 U8.29)
PC4: Peripherals (R126.1), MCU (CN11.53 U8.44)
PC5: MotorCtrl (C6.2 R1.2), MCU (CN11.52 U8.45)
PC6: Audio (R56.2), MotorCtrl (CN1.3), MCU (CN10.2 JP15.1 U8.96)
PC7: MotorCtrl (CN1.7), MCU (CN10.3 JP16.1 U8.97)
PC8: MotorCtrl (CN1.11), MCU (CN10.4 JP17.1 U8.98)
PC9: MCU (CN10.5 U8.99), SD&Smart_Card (CN13.8 R131.2)
PC10: RS232&IrDA (U13.3), MCU (CN10.17 U8.111), SD&Smart_Card (CN13.1 R132.2)
PC11: MCU (CN10.18 JP22.1 U8.112), SD&Smart_Card (CN13.2 R133.2)
PC12: MCU (CN10.20 U8.113), SD&Smart_Card (CN13.5)
PC13: MCU (CN10.56 R11.1 U8.7), LCD&Joystick (R111.2)
PD2: MotorCtrl (C60.2 CN1.27 JP20.1), MCU (CN10.25 U8.116), SD&Smart_Card (CN13.3 R134.2)
PD3: MCU (CN10.26 U8.117), LCD&Joystick (R100.2)
PD4: SRAM&Flash (U1.A2 U2.G2 U3.8), MCU (CN10.27 U8.118), LCD&Joystick (CN16.4)
PD5: SRAM&Flash (U1.G5 U2.A5 U3.18), MCU (CN10.28 U8.119), LCD&Joystick (R80.1)
PD6: SRAM&Flash (JP7.1 R18.1 U2.A4), MCU (CN10.29 U8.122)
PD7: SRAM&Flash (R22.1), MCU (CN10.31 U8.123)
PE0: SRAM&Flash (U1.A1), MCU (CN10.47 U8.141)
PE1: SRAM&Flash (U1.B2), MCU (CN10.24 U8.142)
PF6: Peripherals (R96.2), MCU (CN10.65 U8.18)
PF7: Peripherals (R97.2), MCU (CN10.66 U8.19)
PF8: Peripherals (R98.2), MCU (CN10.67 U8.20)
PF9: Peripherals (R99.2), MCU (CN10.68 U8.21)
PF10: MCU (CN11.67 U8.22), LCD&Joystick (R78.1 U18.6)
PF11: MCU (CN6.9 CN11.46 U8.49), SD&Smart_Card (R129.1)
PG6: SRAM&Flash (JP7.3 R17.1), MCU (CN11.4 U8.91)
PG7: MCU (CN11.3 U8.92), LCD&Joystick (R101.2)
PG8: MCU (CN11.2 U8.93), LCD&Joystick (R106.2)
PG9: SRAM&Flash (R21.1), MCU (CN10.32 U8.124)
PG10: SRAM&Flash (R15.1), MCU (CN10.33 U8.125)
PG11: Audio (R128.2), MCU (CN10.34 U8.126)
PG12: MCU (CN10.35 U8.127), LCD&Joystick (R77.1)
PG13: MCU (CN10.36 U8.128), LCD&Joystick (R103.2)
PG14: MCU (CN10.37 U8.129), LCD&Joystick (R102.2)
PG15: MCU (CN10.38 U8.132), LCD&Joystick (R104.2)
RESET#: JTAG&SWD (CN7.10 CN9.15 JP19.2), MCU (6 pins), LCD&Joystick (CN16.5)

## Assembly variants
F103ZGT6: not fitted C1 C3 C4 C5 C9 C13 C22 C51 C55 C58 C60 C91 JP9 JP10 JP23 JP24 JP25 JP26 JP27 R2 R10 R25 R33 R50 R55 R57 R61 R62 R74 R75 R76 R78 R105 TP1 TP2 TP3 TP4 TP5 TP6 TP7 TP8 TP9 TP10 TP11 TP12 TP13 TP14 TP15 TP16 U18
